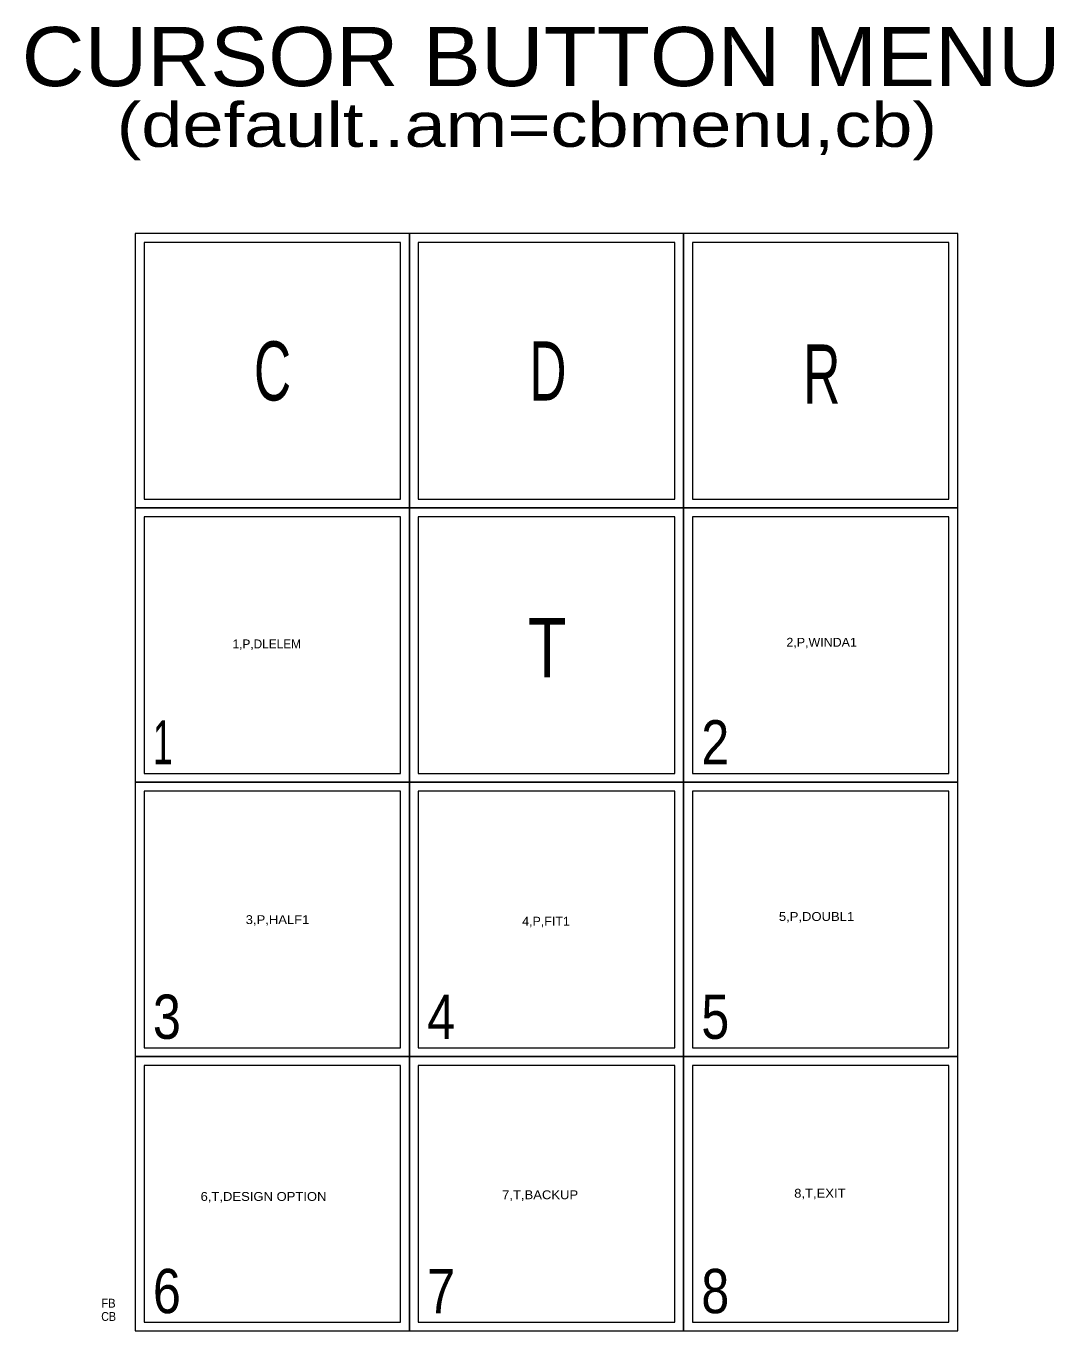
# Model space of a CAD drawing. Extents: x -1.2 to 59.9, y -11 to 7.1.
# Drawn here: x -1.22 to 10.39, y -9.31 to 5.42 of the extents above; entities that cross this region are included whole.
import ezdxf

# ---------------------------------------------------------------- set-up
doc = ezdxf.new("R2010")
doc.units = 0
doc.header["$LTSCALE"] = 0.2
doc.layers.add('1', color=7, linetype='Continuous', lineweight=13)
doc.layers.add('4', color=7, linetype='Continuous', lineweight=13)
doc.layers.add('63', color=7, linetype='Continuous')

msp = doc.modelspace()

# ---------------------------------------------------------------- linework, layer by layer
at = {"layer": '4'}
for points in [[(0.0159, -0.0175), (3.1134, -0.0175), (3.1134, 3.08), (0.0159, 3.08)], [(0.1159, 0.0825), (3.0134, 0.0825), (3.0134, 2.98), (0.1159, 2.98)], [(3.1134, -0.0175), (6.2109, -0.0175), (6.2109, 3.08), (3.1134, 3.08)], [(3.2134, 0.0825), (6.1109, 0.0825), (6.1109, 2.98), (3.2134, 2.98)], [(6.2109, -0.0175), (9.3084, -0.0175), (9.3084, 3.08), (6.2109, 3.08)], [(6.3109, 0.0825), (9.2084, 0.0825), (9.2084, 2.98), (6.3109, 2.98)], [(0.0159, -3.115), (3.1134, -3.115), (3.1134, -0.0175), (0.0159, -0.0175)], [(0.1159, -3.015), (3.0134, -3.015), (3.0134, -0.1175), (0.1159, -0.1175)], [(3.1134, -3.115), (6.2109, -3.115), (6.2109, -0.0175), (3.1134, -0.0175)], [(3.2134, -3.015), (6.1109, -3.015), (6.1109, -0.1175), (3.2134, -0.1175)], [(6.2109, -3.115), (9.3084, -3.115), (9.3084, -0.0175), (6.2109, -0.0175)], [(6.3109, -3.015), (9.2084, -3.015), (9.2084, -0.1175), (6.3109, -0.1175)], [(0.0159, -6.2125), (3.1134, -6.2125), (3.1134, -3.115), (0.0159, -3.115)], [(0.1159, -6.1125), (3.0134, -6.1125), (3.0134, -3.215), (0.1159, -3.215)], [(3.1134, -6.2125), (6.2109, -6.2125), (6.2109, -3.115), (3.1134, -3.115)], [(3.2134, -6.1125), (6.1109, -6.1125), (6.1109, -3.215), (3.2134, -3.215)], [(6.2109, -6.2125), (9.3084, -6.2125), (9.3084, -3.115), (6.2109, -3.115)], [(6.3109, -6.1125), (9.2084, -6.1125), (9.2084, -3.215), (6.3109, -3.215)], [(0.0159, -9.31), (3.1134, -9.31), (3.1134, -6.2125), (0.0159, -6.2125)], [(0.1159, -9.21), (3.0134, -9.21), (3.0134, -6.3125), (0.1159, -6.3125)], [(3.1134, -9.31), (6.2109, -9.31), (6.2109, -6.2125), (3.1134, -6.2125)], [(3.2134, -9.21), (6.1109, -9.21), (6.1109, -6.3125), (3.2134, -6.3125)], [(6.2109, -9.31), (9.3084, -9.31), (9.3084, -6.2125), (6.2109, -6.2125)], [(6.3109, -9.21), (9.2084, -9.21), (9.2084, -6.3125), (6.3109, -6.3125)]]:
    msp.add_lwpolyline(points, close=True, dxfattribs=at)

# ---------------------------------------------------------------- texts
at = {"layer": '1', "width": 1.25}
msp.add_text('(default..am=cbmenu,cb)', height=0.5, dxfattribs=at).set_placement((-0.1939, 4.0586))
at = {"layer": '4'}
for s, height, width, p in [('CURSOR BUTTON MENU', 0.668, 1.1, (-1.2666, 4.744)), ('C', 0.668, 0.65, (1.3577, 1.1945)), ('D', 0.668, 0.65, (4.4687, 1.1945)), ('R', 0.668, 0.65, (7.5626, 1.1593)), ('T', 0.668, 0.8, (4.4515, -1.9293)), ('1', 0.5, 0.6, (0.2159, -2.915)), ('2', 0.5, 0.85, (6.4109, -2.915)), ('3', 0.5, 0.85, (0.2159, -6.0125)), ('4', 0.5, 0.85, (3.3134, -6.0125)), ('5', 0.5, 0.85, (6.4109, -6.0125)), ('6', 0.5, 0.85, (0.2159, -9.11)), ('7', 0.5, 0.85, (3.3134, -9.11)), ('8', 0.5, 0.85, (6.4109, -9.11))]:
    msp.add_text(s, height=height, dxfattribs=dict(at, width=width)).set_placement(p)
at = {"layer": '63'}
msp.add_text('1,P,DLELEM', height=0.1, dxfattribs=at).set_placement((1.116, -1.6035))
for s, width, p in [('2,P,WINDA1', 1.05, (7.3722, -1.5849)), ('3,P,HALF1', 1.1, (1.2643, -4.7165)), ('4,P,FIT1', 1.05, (4.3873, -4.7341)), ('5,P,DOUBL1', 1.1, (7.2873, -4.6812)), ('6,T,DESIGN OPTION', 1.1, (0.7546, -7.8421)), ('7,T,BACKUP', 1.1, (4.161, -7.8232)), ('8,T,EXIT', 1.1, (7.46, -7.8056)), ('FB', 0.95, (-0.3676, -9.0471)), ('CB', 0.9, (-0.3676, -9.1971))]:
    msp.add_text(s, height=0.1, dxfattribs=dict(at, width=width)).set_placement(p)

doc.saveas('drawing.dxf')
